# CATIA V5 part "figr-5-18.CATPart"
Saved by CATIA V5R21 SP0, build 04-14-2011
Part number: Part1
Bounding box of the stored display mesh (mm): x -50 to 50, y -70 to 70, z -20 to 40
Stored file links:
  D:\CATIA V5R21 E-RESOURCES\CATIA-V5R21\catia-v5r21-prt\c05-catia-v5r20-prt\catia-v5r21-figr-5-18.CATPart
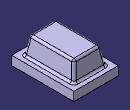
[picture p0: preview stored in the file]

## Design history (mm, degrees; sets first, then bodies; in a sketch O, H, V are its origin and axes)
Body1 (main body)
  Sketch1 on xy-plane, origin (0, 0, 0), H (1, 0, 0), V (0, 1, 0)
    line L1 (50, 70) -> (50, -70)
    line L2 (50, -70) -> (-50, -70)
    line L3 (-50, -70) -> (-50, 70)
    line L4 (-50, 70) -> (50, 70)
    length L2 = 100
    length L1 = 140
    vertical: L1 V, L3 V
    horizontal: L2 H, L4 H
    equidistance: L1 L3 O, L2 L4 O
  Pad1: profile Sketch1, direction (0, 0, -1), length 20
  Sketch2 on face of Pad1, origin (0, 0, 0), H (1, 0, 0), V (0, 1, 0)
    line L1 (30, 50) -> (30, -50)
    line L2 (30, -50) -> (-30, -50)
    line L3 (-30, -50) -> (-30, 50)
    line L4 (-30, 50) -> (30, 50)
    length L2 = 60
    length L1 = 100
    vertical: L1 V, L3 V
    horizontal: L2 H, L4 H
    equidistance: L1 L3 O, L2 L4 O
  Pad2: profile Sketch2, direction (0, 0, 1), length 40, opposite side up to face of Pad1
  Draft1: Angle 9, Neutral face of Pad2, PullDir face of Pad2, SupportToDraft (face of Pad2; face of Pad2; face of Pad2; face of Pad2)
  Fillet1: radius 5, on edge [face of Pad2 | face of Pad2] (x4)
  Fillet2: radius 5, on edge [face of Pad2 | face of Pad2] (x4)
  Fillet3: radius 5, on edge [face of Pad2 | face of Pad1] (x4)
